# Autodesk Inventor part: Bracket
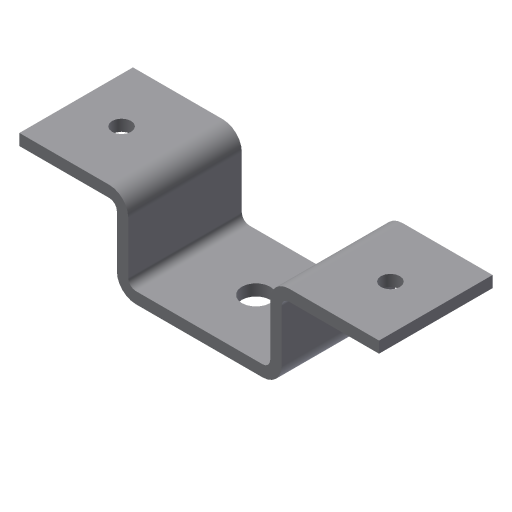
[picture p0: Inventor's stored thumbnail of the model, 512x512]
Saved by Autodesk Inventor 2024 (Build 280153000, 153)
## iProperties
Shininess: 64.0
Length Units: 11269
Angle Units: 11279
Time Units: 11290
Mass Units: 11283
Length Display Precision: 3
Angle Display Precision: 2
Compacted: True
Part Number: Bracket
Document SubType Name: Modeling
Created: 2003-01
Designer: Owner
Density: 1 g/cm^3
Material: Generic
Appearance: Default
Density: 0.0
Volumn: 0.0
Area: 0.0
PropertySet Name: Model Information
Control State: 0
Master: False
Checked Out: False
Author: Owner
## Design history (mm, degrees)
sketch "Sketch2"
  geometry: L1 (487.39, 112.858)-(199.89, 112.858); L2 (199.89, 112.858)-(199.89, -95.142); L3 (199.89, -95.142)-(-175.11, -95.142); L4 (-175.11, -95.142)-(-175.11, 112.858); L5 (-175.11, 112.858)-(-462.61, 112.858); L6 (-462.61, 82.858)-(-205.11, 82.858); L7 (-205.11, 82.858)-(-205.11, -125.142); L8 (-205.11, -125.142)-(229.89, -125.142); L9 (229.89, -125.142)-(229.89, 82.858); L10 (229.89, 82.858)-(487.39, 82.858); L11 (487.39, 112.858)-(487.39, 82.858); L12 (-462.61, 112.858)-(-462.61, 82.858)
  constraints: 24 end point, 5 parallel, 3 perpendicular, 2 collinear, 2 equal length, 1 horizontal, 4 other
  dimensions: "d0" = 375 distance between parallel lines of L4 L2; "d1" = 950 distance of L5.end L1.start; "d2" = 30 distance between parallel lines of L1 L10; "d3" = 238 distance between parallel lines of L5 L8
extrude "Extrusion1" new body sketch "Sketch2" stored distance "d4" = 300; taper "d5" = 0 deg
fillet "Fillet1" dims "d6" = 20
fillet "Fillet2" dims "d7" = 50
sketch "Sketch3"
  geometry: L1 (237.5, 300)-(0, 300) reference; L2 (0, 300)-(0, 0) reference; 1 further point
  dimensions: "d8" = 120 distance from line of L2 point (120, 150); "d9" = 150 distance from line of L1 point (120, 150)
hole "Hole1" sketch "Sketch3" diameter "d10" = 50; stored, may be unused: countersink angle "d14" = 82 deg, drill point angle "d16" = 118 deg; dims "d11" = 6, "d12" = 4, "d13" = 2, "d15" = 8
pattern_linear "Rectangular Pattern1" dims "d19" = 710
sketch "Sketch4"
  geometry: L1 (0, -300)-(335, -300) reference; 1 further point
  dimensions: "d20" = 150 distance from line of L1 point (167.5, -150)
hole "Hole2" sketch "Sketch4" at (167.5, -150) diameter "d21" = 75; stored, may be unused: countersink angle "d25" = 82 deg, drill point angle "d27" = 118 deg; dims "d22" = 6, "d23" = 4, "d24" = 2, "d26" = 8
body "Solid1"
